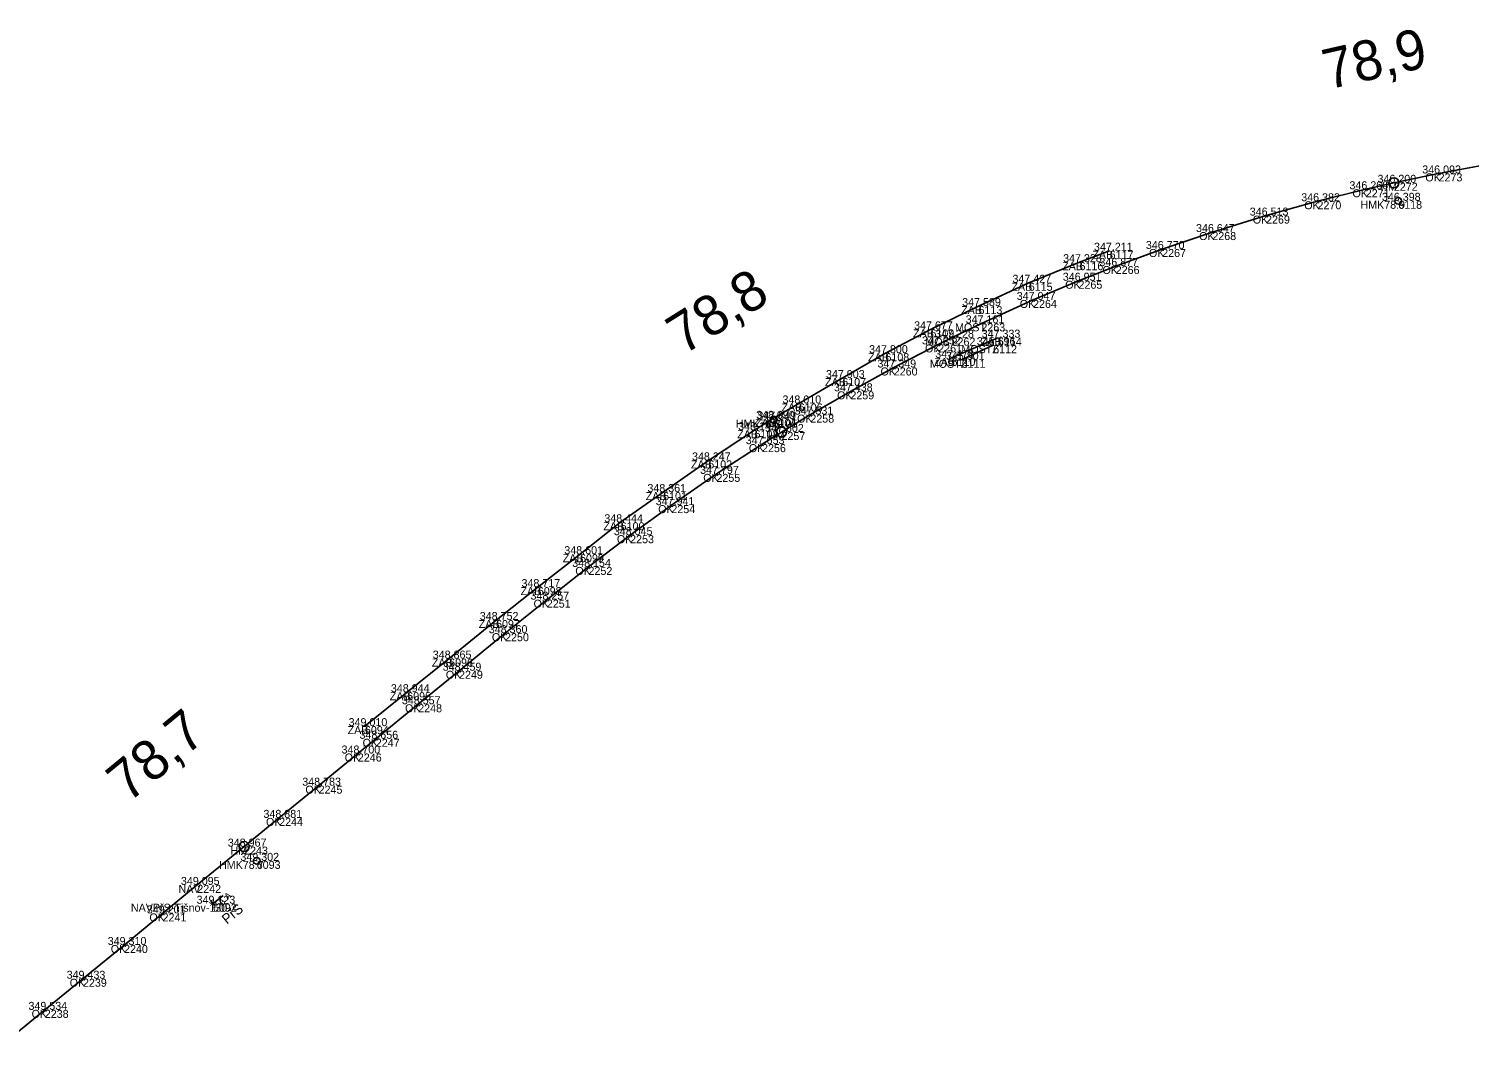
# Model space of a CAD drawing. Extents: x -621782 to -610392, y -1141853 to -1122321.
# Drawn here: x -615618.6 to -615402.5, y -1130200.2 to -1130048.2 of the extents above; entities that cross this region are included whole.
import ezdxf

# ---------------------------------------------------------------- set-up
doc = ezdxf.new("R2010")
doc.units = 0
for name, color, linetype in [('Vrstva 1', 7, 'Continuous'), ('Vrstva 17', 7, 'Continuous'), ('Vrstva 18', 7, 'Continuous'), ('Vrstva 6', 7, 'Continuous'), ('Vrstva 60', 7, 'Continuous'), ('Vrstva 61', 7, 'Continuous'), ('Vrstva 62', 7, 'Continuous'), ('Vrstva 7', 7, 'Continuous')]:
    doc.layers.add(name, color=color, linetype=linetype)

msp = doc.modelspace()

# ---------------------------------------------------------------- linework, layer by layer
at = {"layer": 'Vrstva 1'}
msp.add_lwpolyline([(-615622.06, -1130200.22), (-615616.15, -1130195.37), (-615610.43, -1130190.7), (-615604.27, -1130185.64), (-615598.49, -1130180.9), (-615593.28, -1130176.63), (-615586.26, -1130170.88), (-615581, -1130166.57), (-615575.09, -1130161.74), (-615569.2, -1130156.92), (-615566.51, -1130154.71), (-615560.15, -1130149.53), (-615554.03, -1130144.5), (-615547.12, -1130138.87), (-615540.86, -1130133.84), (-615534.61, -1130128.93), (-615528.36, -1130124.17), (-615522.18, -1130119.66), (-615515.42, -1130114.97), (-615508.58, -1130110.51), (-615505.67, -1130108.69), (-615501.34, -1130106.08), (-615495.34, -1130102.59), (-615488.83, -1130099.01), (-615482.16, -1130095.55), (-615480.16, -1130094.55), (-615475.69, -1130092.39), (-615467.94, -1130088.88), (-615461.12, -1130086), (-615455.54, -1130083.79), (-615448.57, -1130081.24), (-615441.05, -1130078.7), (-615432.99, -1130076.23), (-615425.28, -1130074.08), (-615418.04, -1130072.28), (-615413.83, -1130071.31), (-615407.12, -1130069.91), (-615399.04, -1130068.4)], dxfattribs=at)
at = {"layer": 'Vrstva 17'}
msp.add_line((-615473.2, -1130094.54), (-615480.16, -1130097.57), dxfattribs=at)
msp.add_lwpolyline([(-615568.14, -1130152.81), (-615561.8, -1130147.72), (-615555.51, -1130142.68), (-615548.48, -1130136.89), (-615542.21, -1130131.96), (-615535.88, -1130127.02), (-615529.79, -1130122.23), (-615523.42, -1130117.7), (-615516.64, -1130112.95), (-615509.71, -1130108.42), (-615507.02, -1130106.72), (-615503.07, -1130104.41), (-615496.55, -1130100.6), (-615490.08, -1130096.87), (-615483.33, -1130093.29), (-615476.12, -1130089.8), (-615468.58, -1130086.31), (-615460.97, -1130083.22), (-615456.45, -1130081.5)], dxfattribs=at)
at = {"layer": 'Vrstva 18'}
msp.add_line((-615478.65, -1130097.86), (-615473.92, -1130095.67), dxfattribs=at)
at = {"layer": 'Vrstva 6'}
for p, q in [((-615591.25, -1130179.06), (-615590.62, -1130179.83)), ((-615589.41, -1130178.19), (-615590.94, -1130179.45))]:
    msp.add_line(p, q, dxfattribs=at)
at = {"layer": 'Vrstva 60'}
for p, q in [((-615413.83, -1130071.31), (-615413.83, -1130071.31)), ((-615407.12, -1130069.91), (-615407.12, -1130069.91)), ((-615418.04, -1130072.28), (-615418.04, -1130072.28)), ((-615425.28, -1130074.08), (-615425.28, -1130074.08)), ((-615413.17, -1130074.01), (-615413.17, -1130074.01)), ((-615432.99, -1130076.23), (-615432.99, -1130076.23)), ((-615441.05, -1130078.7), (-615441.05, -1130078.7)), ((-615456.45, -1130081.5), (-615456.45, -1130081.5)), ((-615448.57, -1130081.24), (-615448.57, -1130081.24)), ((-615460.97, -1130083.22), (-615460.97, -1130083.22)), ((-615455.54, -1130083.79), (-615455.54, -1130083.79)), ((-615468.58, -1130086.31), (-615468.58, -1130086.31)), ((-615461.12, -1130086), (-615461.12, -1130086)), ((-615476.12, -1130089.8), (-615476.12, -1130089.8)), ((-615467.94, -1130088.88), (-615467.94, -1130088.88)), ((-615475.69, -1130092.39), (-615475.69, -1130092.39)), ((-615483.33, -1130093.29), (-615483.33, -1130093.29)), ((-615480.16, -1130094.55), (-615480.16, -1130094.55)), ((-615473.2, -1130094.54), (-615473.2, -1130094.54)), ((-615490.08, -1130096.87), (-615490.08, -1130096.87)), ((-615482.16, -1130095.55), (-615482.16, -1130095.55)), ((-615473.92, -1130095.67), (-615473.92, -1130095.67)), ((-615488.83, -1130099.01), (-615488.83, -1130099.01)), ((-615480.16, -1130097.57), (-615480.16, -1130097.57)), ((-615478.65, -1130097.86), (-615478.65, -1130097.86)), ((-615496.55, -1130100.6), (-615496.55, -1130100.6)), ((-615495.34, -1130102.59), (-615495.34, -1130102.59)), ((-615503.07, -1130104.41), (-615503.07, -1130104.41)), ((-615507.02, -1130106.72), (-615507.02, -1130106.72)), ((-615506.84, -1130106.83), (-615506.84, -1130106.83)), ((-615501.34, -1130106.08), (-615501.34, -1130106.08)), ((-615509.71, -1130108.42), (-615509.71, -1130108.42)), ((-615505.67, -1130108.69), (-615505.67, -1130108.69)), ((-615508.58, -1130110.51), (-615508.58, -1130110.51)), ((-615516.64, -1130112.95), (-615516.64, -1130112.95)), ((-615515.42, -1130114.97), (-615515.42, -1130114.97)), ((-615523.42, -1130117.7), (-615523.42, -1130117.7)), ((-615522.18, -1130119.66), (-615522.18, -1130119.66)), ((-615529.79, -1130122.23), (-615529.79, -1130122.23)), ((-615528.36, -1130124.17), (-615528.36, -1130124.17)), ((-615535.88, -1130127.02), (-615535.88, -1130127.02)), ((-615534.61, -1130128.93), (-615534.61, -1130128.93)), ((-615542.21, -1130131.96), (-615542.21, -1130131.96)), ((-615540.86, -1130133.84), (-615540.86, -1130133.84)), ((-615548.48, -1130136.89), (-615548.48, -1130136.89)), ((-615547.12, -1130138.87), (-615547.12, -1130138.87)), ((-615555.51, -1130142.68), (-615555.51, -1130142.68)), ((-615554.03, -1130144.5), (-615554.03, -1130144.5)), ((-615561.8, -1130147.72), (-615561.8, -1130147.72)), ((-615560.15, -1130149.53), (-615560.15, -1130149.53)), ((-615568.14, -1130152.81), (-615568.14, -1130152.81)), ((-615566.51, -1130154.71), (-615566.51, -1130154.71)), ((-615569.2, -1130156.92), (-615569.2, -1130156.92)), ((-615575.09, -1130161.74), (-615575.09, -1130161.74)), ((-615581, -1130166.57), (-615581, -1130166.57)), ((-615586.26, -1130170.88), (-615586.26, -1130170.88)), ((-615584.37, -1130173.02), (-615584.37, -1130173.02)), ((-615593.28, -1130176.63), (-615593.28, -1130176.63)), ((-615598.49, -1130180.9), (-615598.49, -1130180.9)), ((-615590.94, -1130179.45), (-615590.94, -1130179.45)), ((-615604.27, -1130185.64), (-615604.27, -1130185.64)), ((-615610.43, -1130190.7), (-615610.43, -1130190.7)), ((-615616.15, -1130195.37), (-615616.15, -1130195.37))]:
    msp.add_line(p, q, dxfattribs=at)
at = {"layer": 'Vrstva 7'}
for p, q in [((-615413.22, -1130074.02), (-615413.12, -1130074)), ((-615506.88, -1130106.86), (-615506.8, -1130106.8)), ((-615584.41, -1130173.05), (-615584.33, -1130172.98))]:
    msp.add_line(p, q, dxfattribs=at)
for centre, radius in [((-615413.83, -1130071.31), 0.75), ((-615413.17, -1130074.01), 0.5), ((-615506.84, -1130106.83), 0.5), ((-615505.67, -1130108.69), 0.75), ((-615586.26, -1130170.88), 0.75), ((-615584.37, -1130173.02), 0.5)]:
    msp.add_circle(centre, radius, dxfattribs=at)

# ---------------------------------------------------------------- texts
at = {"layer": 'Vrstva 6'}
for s, height, p in [('  A A ', 1, (-615590.3, -1130180.22)), ('PřS', 1.5, (-615588.84, -1130182.59))]:
    msp.add_text(s, height=height, rotation=39.3229, dxfattribs=at).set_placement(p)
at = {"layer": 'Vrstva 60'}
for s, p in [('2272', (-615413.83, -1130072.51)), ('2273', (-615407.12, -1130071.1)), ('2271', (-615418.04, -1130073.48)), ('2270', (-615425.28, -1130075.28)), ('6118', (-615413.17, -1130075.21)), ('2269', (-615432.99, -1130077.43)), ('2268', (-615441.05, -1130079.9)), ('6117', (-615456.45, -1130082.7)), ('2267', (-615448.57, -1130082.44)), ('6116', (-615460.97, -1130084.42)), ('2266', (-615455.54, -1130084.99)), ('6115', (-615468.58, -1130087.51)), ('2265', (-615461.12, -1130087.2)), ('6113', (-615476.12, -1130091)), ('2264', (-615467.94, -1130090.08)), ('2263', (-615475.69, -1130093.59)), ('6109', (-615483.33, -1130094.49)), ('2262', (-615480.16, -1130095.75)), ('6114', (-615473.2, -1130095.74)), ('6108', (-615490.08, -1130098.07)), ('2261', (-615482.16, -1130096.75)), ('6112', (-615473.92, -1130096.87)), ('2260', (-615488.83, -1130100.21)), ('6110', (-615480.16, -1130098.77)), ('6111', (-615478.65, -1130099.06)), ('6107', (-615496.55, -1130101.8)), ('2259', (-615495.34, -1130103.79)), ('6106', (-615503.07, -1130105.61)), ('6104', (-615507.02, -1130107.92)), ('6105', (-615506.84, -1130108.03)), ('2258', (-615501.34, -1130107.28)), ('6103', (-615509.71, -1130109.62)), ('2257', (-615505.67, -1130109.89)), ('2256', (-615508.58, -1130111.71)), ('6102', (-615516.64, -1130114.15)), ('2255', (-615515.42, -1130116.17)), ('6101', (-615523.42, -1130118.9)), ('2254', (-615522.18, -1130120.86)), ('6100', (-615529.79, -1130123.43)), ('2253', (-615528.36, -1130125.37)), ('6099', (-615535.88, -1130128.22)), ('2252', (-615534.61, -1130130.13)), ('6098', (-615542.21, -1130133.16)), ('2251', (-615540.86, -1130135.04)), ('6097', (-615548.48, -1130138.09)), ('2250', (-615547.12, -1130140.07)), ('6096', (-615555.51, -1130143.88)), ('2249', (-615554.03, -1130145.7)), ('6095', (-615561.8, -1130148.92)), ('2248', (-615560.15, -1130150.73)), ('6094', (-615568.14, -1130154.01)), ('2247', (-615566.51, -1130155.91)), ('2246', (-615569.2, -1130158.12)), ('2245', (-615575.09, -1130162.94)), ('2244', (-615581, -1130167.78)), ('2243', (-615586.26, -1130172.08)), ('6093', (-615584.37, -1130174.22)), ('2242', (-615593.28, -1130177.83)), ('2241', (-615598.49, -1130182.1)), ('6092', (-615590.94, -1130180.65)), ('2240', (-615604.27, -1130186.84)), ('2239', (-615610.43, -1130191.9)), ('2238', (-615616.15, -1130196.57))]:
    msp.add_text(s, height=1.2, dxfattribs=at).set_placement(p)
at = {"layer": 'Vrstva 61'}
for s, p in [('346.093', (-615409.57, -1130069.91)), ('346.266', (-615420.49, -1130072.28)), ('346.200', (-615416.28, -1130071.31)), ('346.382', (-615427.72, -1130074.08)), ('346.398', (-615415.62, -1130074.01)), ('346.513', (-615435.44, -1130076.23)), ('346.647', (-615443.5, -1130078.7)), ('346.770', (-615451.02, -1130081.24)), ('347.328', (-615463.43, -1130083.22)), ('347.211', (-615458.8, -1130081.5)), ('346.877', (-615457.99, -1130083.79)), ('347.427', (-615471.03, -1130086.31)), ('346.951', (-615463.48, -1130086)), ('347.589', (-615478.57, -1130089.8)), ('347.047', (-615470.39, -1130088.88)), ('347.677', (-615485.78, -1130093.29)), ('347.161', (-615478.05, -1130092.39)), ('347.252', (-615484.6, -1130095.55)), ('347.228', (-615482.61, -1130094.55)), ('345.596', (-615476.38, -1130095.67)), ('347.333', (-615475.65, -1130094.54)), ('347.800', (-615492.53, -1130096.87)), ('347.478', (-615482.61, -1130097.57)), ('345.801', (-615481.01, -1130097.86)), ('347.903', (-615499, -1130100.6)), ('347.349', (-615491.28, -1130099.01)), ('347.438', (-615497.8, -1130102.59)), ('348.010', (-615505.52, -1130104.41)), ('348.090', (-615509.47, -1130106.72)), ('347.849', (-615509.29, -1130106.83)), ('347.531', (-615503.7, -1130106.08)), ('348.145', (-615512.17, -1130108.42)), ('347.602', (-615508.12, -1130108.69)), ('347.653', (-615511.03, -1130110.51)), ('348.247', (-615519.09, -1130112.95)), ('347.797', (-615517.87, -1130114.97)), ('348.361', (-615525.78, -1130117.7)), ('347.941', (-615524.53, -1130119.66)), ('348.444', (-615532.24, -1130122.23)), ('348.045', (-615530.82, -1130124.17)), ('348.601', (-615538.24, -1130127.02)), ('348.154', (-615537.06, -1130128.93)), ('348.717', (-615544.66, -1130131.96)), ('348.257', (-615543.31, -1130133.84)), ('348.752', (-615550.92, -1130136.89)), ('348.360', (-615549.57, -1130138.87)), ('348.865', (-615557.97, -1130142.68)), ('348.459', (-615556.48, -1130144.5)), ('348.944', (-615564.25, -1130147.72)), ('348.557', (-615562.6, -1130149.53)), ('349.010', (-615570.59, -1130152.81)), ('348.656', (-615568.96, -1130154.71)), ('348.700', (-615571.65, -1130156.92)), ('348.783', (-615577.54, -1130161.74)), ('348.881', (-615583.36, -1130166.57)), ('348.967', (-615588.71, -1130170.88)), ('349.302', (-615586.82, -1130173.02)), ('349.095', (-615595.74, -1130176.63)), ('349.123', (-615593.39, -1130179.45)), ('349.201', (-615600.85, -1130180.9)), ('349.310', (-615606.72, -1130185.64)), ('349.433', (-615612.88, -1130190.7)), ('349.534', (-615618.6, -1130195.37))]:
    msp.add_text(s, height=1.2, dxfattribs=at).set_placement(p)
at = {"layer": 'Vrstva 62'}
for s, p in [('HM', (-615415.86, -1130072.51)), ('OK', (-615409.11, -1130071.1)), ('OK', (-615420.03, -1130073.48)), ('OK', (-615427.26, -1130075.28)), ('HMK78.9', (-615418.84, -1130075.21)), ('OK', (-615434.98, -1130077.43)), ('OK', (-615443.03, -1130079.9)), ('ZAB', (-615459.05, -1130082.7)), ('OK', (-615450.55, -1130082.44)), ('ZAB', (-615463.57, -1130084.42)), ('OK', (-615457.52, -1130084.99)), ('ZAB', (-615471.18, -1130087.51)), ('OK', (-615463.11, -1130087.2)), ('ZAB', (-615478.72, -1130091)), ('OK', (-615469.93, -1130090.08)), ('MOST', (-615479.64, -1130093.59)), ('ZAB', (-615485.93, -1130094.49)), ('MOST', (-615484.1, -1130095.75)), ('ZAB', (-615475.8, -1130095.74)), ('ZAB', (-615492.68, -1130098.07)), ('OK', (-615484.14, -1130096.75)), ('MOSTZ', (-615478.7, -1130096.87)), ('OK', (-615490.81, -1130100.21)), ('MOSTZ', (-615483.43, -1130099.06)), ('ZAB', (-615482.76, -1130098.77)), ('ZAB', (-615499.15, -1130101.8)), ('OK', (-615497.33, -1130103.79)), ('ZAB', (-615505.67, -1130105.61)), ('HMK78.8', (-615512.51, -1130108.03)), ('ZAB', (-615509.63, -1130107.92)), ('OK', (-615503.33, -1130107.28)), ('ZAB', (-615512.31, -1130109.62)), ('HM', (-615507.7, -1130109.89)), ('OK', (-615510.56, -1130111.71)), ('ZAB', (-615519.24, -1130114.15)), ('OK', (-615517.4, -1130116.17)), ('ZAB', (-615526.03, -1130118.9)), ('OK', (-615524.16, -1130120.86)), ('ZAB', (-615532.39, -1130123.43)), ('OK', (-615530.35, -1130125.37)), ('ZAB', (-615538.48, -1130128.22)), ('OK', (-615536.59, -1130130.13)), ('ZAB', (-615544.81, -1130133.16)), ('OK', (-615542.85, -1130135.04)), ('ZAB', (-615551.08, -1130138.09)), ('OK', (-615549.1, -1130140.07)), ('ZAB', (-615558.11, -1130143.88)), ('OK', (-615556.01, -1130145.7)), ('ZAB', (-615564.41, -1130148.92)), ('OK', (-615562.13, -1130150.73)), ('ZAB', (-615570.74, -1130154.01)), ('OK', (-615568.49, -1130155.91)), ('OK', (-615571.18, -1130158.12)), ('OK', (-615577.07, -1130162.94)), ('OK', (-615582.98, -1130167.78)), ('HM', (-615588.3, -1130172.08)), ('HMK78.7', (-615590.03, -1130174.22)), ('NAV', (-615596.1, -1130177.83)), ('NAVPřS-Tišnov-130', (-615603.24, -1130180.65)), ('OK', (-615600.47, -1130182.1)), ('OK', (-615606.26, -1130186.84)), ('OK', (-615612.42, -1130191.9)), ('OK', (-615618.13, -1130196.57))]:
    msp.add_text(s, height=1.2, dxfattribs=at).set_placement(p)
at = {"layer": 'Vrstva 7'}
for s, rotation, p in [('78,9', 12.8993, (-615423.71, -1130057.34)), ('78,8', 31.9699, (-615520.39, -1130097.22)), ('78,7', 39.3569, (-615603.66, -1130164.42))]:
    msp.add_text(s, height=6, rotation=rotation, dxfattribs=at).set_placement(p)

doc.saveas('drawing.dxf')
